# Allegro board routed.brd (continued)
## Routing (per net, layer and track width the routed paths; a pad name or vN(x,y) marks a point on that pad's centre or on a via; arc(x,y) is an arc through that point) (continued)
MEMORY.RA12: length 274.6
  TOP w0.15: v1(78.32,73.41) 80.45,73.41 80.84,73.01 80.84,67.52 83.13,65.23 v1(118.01,65.23) ; 114.48,86.2 113.97,85.68 113.97,80.27 114.48,79.75 U20.19 ; 114.48,86.2 U21.19 ; 114.48,86.2 116.56,86.2 118.14,84.61 118.14,72.99 118.01,72.86 v1(118.01,72.13) ; U18.19 v1(90.48,102.53) ; v1(97.53,99.06) 96.72,98.25 96.72,86.8 v1(95.78,85.86) ; U5.62 68.05,94.46 v1(68.93,93.59) ; U22.19 114.48,102.79 116.14,101.14 117.71,101.14 v1(118.44,101.87) 118.44,117.39 117.43,118.41 114.48,118.41 U23.19 ; U17.19 90.48,90.03 90.7,90.03 v1(90.7,89.3) 92.36,87.65 92.36,80.7 91.96,80.31 91.85,80.31 91.22,79.67 91.22,76.99 90.96,76.73 90.68,76.73 90.48,76.93 U16.19 ; U19.19 v1(90.48,112.56)
  BOTTOM w0.15: v1(90.48,112.56) v1(90.48,102.53) 90.48,101.79 ; 90.48,101.79 90.48,96 88.07,93.59 v1(68.93,93.59) ; 90.48,101.79 92.29,101.79 92.68,102.19 92.68,104.09 96.49,107.9 97.43,107.9 97.83,107.51 97.83,100.1 97.53,99.8 v1(97.53,99.06) ; v1(118.44,101.87) 118.44,87.18 118.01,86.74 v1(118.01,72.13) v1(118.01,65.23) ; v1(95.78,85.86) 94.92,86.72 93.28,86.72 v1(90.7,89.3) 89.85,90.16 82.51,90.16 78.32,85.96 78.32,80.13 78.52,79.94 78.52,74.33 78.32,74.14 v1(78.32,73.41)
MEMORY.RA13: length 256.6
  TOP w0.15: U20.18 v1(115.75,79.84) ; U22.18 115.75,102.62 v1(116.51,101.87) ; 94.14,115.73 94.14,90.33 93.55,89.73 ; 94.14,115.73 92.01,115.73 91.75,115.99 U19.18 ; 94.14,115.73 94.44,116.03 v1(94.44,117.27) ; U5.61 64.28,93.19 v1(63.54,93.93) v1(49.14,93.93) ; v1(116.04,115.29) 116.04,116.03 115.75,116.03 U23.18 ; 93.55,89.73 93.55,80.72 92.53,79.7 92.01,79.7 91.75,79.45 U16.18 ; 93.55,89.73 92.01,89.73 91.75,89.99 U17.18 ; U18.18 91.95,104.22 v1(91.95,102.6) ; U21.18 v1(115.75,92.69)
  BOTTOM w0.15: v1(49.14,93.93) 49.14,94.67 48.73,95.08 48.73,114.7 52.03,118 92.13,118 92.87,117.27 v1(94.44,117.27) 114.06,117.27 v1(116.04,115.29) 116.04,108.31 116.51,107.84 v1(116.51,101.87) 116.51,93.44 v1(115.76,92.69) 115.76,91.96 v1(115.75,79.84) ; v1(63.54,93.93) 64.53,94.92 86.76,94.92 87.78,95.94 87.78,98.65 87.66,98.76 87.66,103.69 89.36,105.38 89.36,112.5 90.15,113.29 90.82,113.29 91.22,112.89 91.22,111.71 91.17,111.67 91.17,106.35 91.95,105.57 v1(91.95,102.6)
MEMORY.RA14: length 227.3
  TOP w0.15: 116.47,96.27 116.01,96.27 115.75,96.01 U22.15 ; 116.47,96.27 116.47,97.83 115.84,98.47 112.31,98.47 111.42,99.35 111.42,105.28 111.55,105.41 115.36,105.41 115.75,105.8 U23.15 ; 116.47,96.27 116.5,96.23 v1(116.5,89.6) ; 115.45,72.82 116.09,73.46 116.96,73.46 117.84,74.35 117.84,83.82 v1(116.5,85.16) 115.75,84.41 U21.15 ; 115.45,72.82 115.75,72.52 U20.15 ; 115.45,72.82 v1(112.46,72.82) ; v1(89.73,101.36) 89.73,105.16 90.88,106.31 91.5,106.31 91.75,106.56 U19.15 ; U16.15 91.75,67.59 ; 91.75,67.59 90.01,67.59 89.75,67.85 v1(89.75,72.76) ; 91.75,67.59 v1(93.98,67.59) ; v1(89.73,96.4) 89.73,93.85 89.99,93.59 91.75,93.59 U18.15 91.75,95.97 93.42,95.97 93.55,95.84 93.55,92.8 93.15,92.41 90.09,92.41 89.97,92.28 89.97,88.67 92.06,86.58 92.06,85.33 v1(91.25,84.52) 91.25,83.52 91.75,83.02 U17.15 ; U5.60 v1(64.31,91.92)
  BOTTOM w0.15: v1(116.5,89.6) v1(116.5,85.16) ; v1(64.31,91.92) 67.01,94.62 86.93,94.62 88.08,95.76 88.08,100.15 87.96,100.26 87.96,102.64 88.36,103.03 89.1,103.03 89.73,102.4 v1(89.73,101.36) v1(89.73,96.4) ; v1(112.46,72.82) 112.46,71.97 109.28,68.8 107.56,68.8 105.53,66.76 105.53,66.75 104.38,65.6 72.41,65.6 71.9,66.11 71.9,67.18 72.92,68.19 92.64,68.19 93.25,67.59 v1(93.98,67.59) ; v1(91.25,84.52) 90.2,84.52 89.69,84.02 89.69,80.06 89.75,80.01 v1(89.75,72.76)
MEMORY.RA15: length 192.9
  TOP w0.15: 93.55,102.09 93.25,101.8 92.71,101.8 88.64,97.73 87.12,97.73 86.86,97.47 v1(86.13,97.47) ; 93.55,102.09 93.84,101.8 93.84,99.11 91.31,96.56 90.99,96.56 90.48,96.06 U18.14 ; 93.55,102.09 93.55,110 92.75,110.79 92.14,110.79 90.48,109.14 U19.14 ; v1(115,96.27) 114.78,96.27 114.27,95.76 114.27,94.78 U22.14 ; 90.48,80.59 U17.14 ; 90.48,80.59 81.1,80.59 80.84,80.85 80.84,82.84 80.72,82.97 79.91,82.97 79.79,82.84 79.79,80.85 79.53,80.59 73.49,80.59 70.32,83.77 70.32,87.86 68.79,89.38 U5.58 63.01,89.38 62.81,89.18 v1(62.07,89.18) ; 90.48,80.59 v1(90.48,79.86) ; 90.48,69.97 94.13,69.97 96.5,67.59 98.37,67.59 98.5,67.72 98.5,69.87 98.89,70.27 99.37,70.27 99.77,69.87 99.77,66.83 100.16,66.43 103.58,66.43 104.84,67.7 104.84,69.68 107.26,72.09 v1(114.48,72.09) U20.14 ; 90.48,69.97 v1(90.48,71.6) ; 90.48,69.97 U16.14 ; v1(115,106.14) 114.99,106.14 114.48,106.65 U23.14 ; v1(115,83.7) 115,82.97 114.48,82.97 U21.14
  BOTTOM w0.15: v1(115,106.14) v1(115,96.27) v1(115,83.7) 115,73.98 114.48,73.46 v1(114.48,72.09) ; v1(62.07,89.18) 62.07,94.12 63.47,95.52 85.49,95.52 86.13,96.15 v1(86.13,97.47) ; v1(90.48,79.86) v1(90.48,71.6)
MEMORY.RCS0: length 65.1
  TOP w0.15: U5.51 62.16,80.92 63.3,79.77 63.65,79.77 ; U17.6 80.33,80.58 79.82,80.07 63.95,80.07 63.65,79.77 ; 63.65,79.77 63.65,73.97 70.25,67.37 73.27,67.37 73.67,66.97 73.67,66.3 73.27,65.91 70.49,65.91 70.06,66.34 67.4,66.34 67.01,65.94 67.01,65.27 67.4,64.87 77.66,64.87 80.33,67.54 U16.6
MEMORY.RCS1: length 47.7
  TOP w0.15: U5.50 60.89,84.19 60.38,84.69 v1(60.16,84.69) ; U18.6 v1(80.33,96.9) ; U19.6 v1(80.33,106.14) ; v1(60.16,89.92) 69.41,89.92 70.05,90.55 v1(70.05,96.9)
  BOTTOM w0.15: v1(70.05,96.9) 79.59,96.9 ; 79.59,96.9 v1(80.33,96.9) ; 79.59,96.9 79.59,105.41 v1(80.33,106.14) ; v1(60.16,89.92) v1(60.16,84.69)
MEMORY.RCS2: length 71.3
  TOP w0.15: v1(72.94,66.64) 70.44,66.64 62.95,74.13 62.95,77.5 59.62,80.83 U5.49 ; U21.6 104.33,80.07 103.59,79.34 v1(103.59,70.4) 103.82,70.4 104.33,69.89 U20.6
  BOTTOM w0.15: v1(72.94,66.64) 73.67,66.64 73.88,66.43 103.19,66.43 103.59,66.83 v1(103.59,70.4)
MEMORY.RCS3: length 154
  TOP w0.15: U23.6 104.33,106.31 105.06,105.57 105.06,101.53 105.36,101.23 ; 105.36,101.23 105.36,98.81 104.33,97.78 U22.6 ; 105.36,101.23 107.98,101.23 108.87,102.12 108.87,105.37 109.5,106 111.83,106 112.47,106.64 112.47,108.73 113.73,110 v1(116.81,110) ; v1(69.28,86.11) 60.13,86.11 58.35,84.33 U5.48
  BOTTOM w0.15: v1(116.81,110) 116.81,109.27 117.24,108.83 117.24,78.82 115.91,77.48 115.91,70.8 109.81,64.7 72.33,64.7 69.28,67.75 v1(69.28,86.11)
MEMORY.RD0: length 243.3
  TOP w0.15: v1(105.59,97.27) U22.7 105.59,93.56 105.85,93.31 113.99,93.31 115,92.29 115,90.01 116.15,88.87 117.25,88.87 117.55,89.17 ; 111.71,67.59 111.41,67.59 111.41,69.84 109.76,71.49 107.12,71.49 105.59,69.97 U20.7 ; 111.71,67.59 117.47,67.59 118.75,68.87 118.75,87.97 117.55,89.17 ; 111.71,67.59 111.71,66.8 110.44,65.53 83.37,65.53 81.59,67.31 U16.7 ; v1(57.31,117.27) 57.31,113 57.08,112.76 U5.81 ; v1(92.5,109.76) 92.5,106.59 91.62,105.7 91.22,105.31 91.22,101.75 87.66,98.2 83.25,98.2 81.59,96.55 U18.7 ; 117.55,89.17 117.55,97.23 114.37,100.4 v1(112.68,100.4)
  BOTTOM w0.15: v1(112.68,100.4) 112.33,100.75 112.33,113.43 109.15,116.6 97.61,116.6 97.55,116.54 91.07,116.54 90.33,117.27 v1(57.31,117.27) ; v1(105.59,97.27) 105.59,93.16 104.71,92.27 103.89,92.27 102.24,93.92 102.24,112.99 101.73,113.49 96.24,113.49 v1(92.5,109.76)
MEMORY.RD1: length 140.1
  TOP w0.15: v1(85.3,96.4) 85.3,94.78 ; 85.3,94.78 U18.10 ; 85.3,94.78 84.88,94.78 84.88,89.99 85.14,89.73 85.53,89.73 85.92,90.13 85.92,92.15 86.94,93.16 v1(92.79,93.16) ; U22.10 109.41,95.97 109.69,95.97 v1(109.69,96.7) ; v1(61.62,99.3) 55.81,105.12 U5.82 ; v1(109.41,70.7) U20.10 109.41,67.53 108.01,66.13 86.8,66.13 85.41,67.53 U16.10
  BOTTOM w0.15: v1(109.41,70.7) 111.16,72.45 111.16,85.42 110.95,85.62 ; v1(92.79,93.16) 93.82,94.19 98.16,94.19 100.83,91.53 100.83,89.01 104.51,85.33 110.65,85.33 110.95,85.62 ; 110.95,85.62 110.95,87.65 109.69,88.9 v1(109.69,96.7) ; v1(85.3,96.4) 84.93,96.02 64.9,96.02 v1(61.62,99.3)
MEMORY.RD2: length 231.9
  TOP w0.15: U18.23 85.41,103.11 85.88,102.64 v1(85.88,102.6) ; U22.23 109.41,102.97 109.85,102.52 v1(109.85,101.79) ; U20.23 109.41,76.39 110.04,75.75 v1(112.03,75.75) ; v1(54.54,108.24) U5.83 ; v1(72.95,73.75) 72.95,74.48 ; 72.95,74.48 v1(64.68,74.48) ; 72.95,74.48 73.25,74.78 83.74,74.78 84.89,75.92 84.89,76.28 85.41,76.8 U16.23
  BOTTOM w0.15: v1(109.85,101.79) 110.93,101.79 111.73,101 111.73,75.02 ; 111.73,75.02 111.73,71.81 109.31,69.4 107.17,69.4 104.62,66.85 104.62,66.79 103.74,65.91 72.6,65.91 72.2,66.3 72.2,67.01 73.09,67.9 88.55,67.9 89.58,66.86 94.61,66.86 95.01,67.26 95.01,67.7 94.22,68.5 75.87,68.5 72.95,71.42 v1(72.95,73.75) ; 111.73,75.02 112.03,75.02 v1(112.03,75.75) ; 58.01,108.24 80.24,108.24 v1(85.88,102.6) ; 58.01,108.24 58.01,83.76 59.4,82.36 59.46,82.36 63.65,78.17 63.65,75.51 v1(64.68,74.48) ; 58.01,108.24 v1(54.54,108.24)
MEMORY.RD3: length 278.1
  TOP w0.15: 105.59,74.72 U20.26 ; 105.59,74.72 v1(117.11,74.72) ; 105.59,74.72 v1(104.33,74.72) ; v1(60.58,65.73) 65.59,65.73 66.83,64.5 118.35,64.5 118.75,64.89 118.75,65.97 117.86,66.86 v1(117.11,66.86) ; U22.26 105.59,105.77 106.11,106.29 106.11,110.07 107.51,111.46 v1(116.92,111.46) ; U16.26 81.59,79.41 87.07,79.41 87.19,79.28 87.19,77.39 88.85,75.74 95.29,75.74 95.68,75.34 95.68,74.69 95.18,74.18 v1(94.13,74.18) ; U18.26 81.59,105.5 82.1,106 85.29,106 85.92,106.64 85.92,110.78 86.81,111.67 86.91,111.67 87.31,112.07 87.31,118.2 86.8,118.7 57.08,118.7 53.27,114.89 U5.84 v1(53.27,109.03)
  BOTTOM w0.15: v1(53.27,109.03) 53.27,85.2 57.21,81.26 57.28,81.26 60.58,77.96 v1(60.58,65.73) ; v1(94.13,74.18) 103.05,74.18 103.59,74.72 v1(104.33,74.72) ; v1(116.92,111.46) 116.92,110.73 117.14,110.73 117.54,110.33 117.54,76.86 117.11,76.44 v1(117.11,74.72) v1(117.11,66.86)
MEMORY.RD4: length 154
  TOP w0.15: U17.7 81.59,83.65 83.25,85.3 88.83,85.3 v1(90.43,83.7) ; U23.7 105.59,109.03 104.33,110.3 v1(100.78,110.3) ; v1(104.31,83.4) 105.2,83.4 105.59,83 U21.7 ; U19.7 v1(81.59,110.12) ; v1(56.55,115.02) v1(56.55,109.31) ; U5.1 v1(52,115.02)
  BOTTOM w0.15: v1(104.31,83.4) 100.53,83.4 ; 100.53,83.4 100.23,83.1 100.23,76.53 98.83,75.14 97.38,75.14 96.58,75.93 96.58,77.54 v1(90.43,83.7) ; 100.53,83.4 100.53,91.31 98.24,93.59 95.9,93.59 94.74,92.43 92.45,92.43 92.06,92.83 92.06,93.49 95.99,97.43 96.99,97.43 98.26,98.7 98.26,108.36 ; 98.26,108.36 98.84,108.36 v1(100.78,110.3) ; 98.26,108.36 92.36,108.36 91.47,109.25 91.47,111.37 91.52,111.41 91.52,113.08 91.01,113.59 89.9,113.59 88.76,112.45 88.76,110.61 87.17,109.02 81.85,109.02 81.59,109.28 v1(81.59,110.12) 80.77,110.12 80.45,110.43 57.67,110.43 v1(56.55,109.31) ; v1(52,115.02) v1(56.55,115.02)
MEMORY.RD5: length 188
  TOP w0.15: v1(104.31,93) 110.56,93 111.19,92.37 111.19,88.39 109.92,87.12 109.91,87.12 109.41,86.62 U21.10 v1(109.41,80.16) ; U19.10 85.41,109.64 83.37,111.67 v1(79.85,111.67) ; v1(88.48,84.56) 86.99,84.56 85.41,82.98 U17.10 ; v1(60.26,116.3) v1(60.26,113.55) ; U5.2 v1(50.73,113.55) ; U23.10 v1(109.41,110.32)
  BOTTOM w0.15: v1(79.85,111.67) 62.14,111.67 v1(60.26,113.55) v1(50.73,113.55) ; v1(109.41,80.16) 108.67,80.16 107.96,80.87 105.55,80.87 101.99,77.31 101.99,77.25 99.58,74.84 96.28,74.84 95.08,76.04 94.46,76.04 92.55,74.13 92.55,72.52 90.9,70.87 90.06,70.87 88.29,72.64 88.29,79.88 88.59,80.19 88.59,83.72 88.48,83.83 v1(88.48,84.56) ; v1(60.26,116.3) 89.64,116.3 89.71,116.24 99.95,116.24 100.01,116.3 108.97,116.3 111.25,114.02 111.25,111.34 110.23,110.32 v1(109.41,110.32) 109.41,106.58 105.06,102.23 105.06,101.12 104.17,100.23 104.11,100.23 103.72,99.84 103.72,94.33 104.31,93.74 v1(104.31,93)
MEMORY.RD6: length 146.1
  TOP w0.15: v1(97.02,107.17) v1(97.02,112.46) ; U17.23 85.41,92.45 86.42,93.46 88.21,93.46 88.47,93.72 88.47,96.29 89.61,97.43 90.88,97.43 v1(93.11,99.66) ; v1(108.96,88.27) 108.96,89 109.41,89.44 U21.23 ; U23.23 v1(109.41,114.23) ; U19.23 85.41,116.03 85.17,115.8 v1(85.17,114.41) ; U5.3 v1(49.46,114.28)
  BOTTOM w0.15: 91.52,114.11 86.2,114.11 85.9,114.41 v1(85.17,114.41) 61.66,114.41 61.53,114.28 v1(49.46,114.28) ; 91.52,114.11 91.64,114.23 v1(109.41,114.23) ; 91.52,114.11 91.82,113.81 91.82,110.81 91.77,110.77 91.77,109.42 92.17,109.02 93.58,109.02 v1(97.02,112.46) 98.06,112.46 98.79,113.19 101.54,113.19 101.94,112.8 101.94,93.79 104.23,91.5 106.8,91.5 108.96,89.34 v1(108.96,88.27) ; v1(97.02,107.17) 93.11,103.26 v1(93.11,99.66)
MEMORY.RD7: length 154.9
  TOP w0.15: v1(62.45,100.43) 57.62,105.26 57.62,115.66 v1(58.49,116.54) 58.49,117.37 57.86,118 56.92,118 55.27,116.35 55.27,107.84 54.64,107.21 50.6,107.21 48.19,109.62 U5.4 ; U21.26 v1(105.59,89.6) ; v1(77.7,97.63) 78.47,97.63 79.35,96.74 79.35,96.11 79.66,95.81 79.66,93.8 80.45,93 81.09,93 81.59,92.5 U17.26 ; v1(101.21,112.46) 105.09,112.46 105.59,112.97 v1(105.59,115.27) U23.26 ; U19.26 v1(81.59,115.22)
  BOTTOM w0.15: 81.59,116 61.81,116 61.38,115.57 59.47,115.57 v1(58.49,116.54) ; 81.59,116 v1(81.59,115.22) ; 81.59,116 85.77,116 87.23,114.53 104.86,114.53 v1(105.59,115.27) ; v1(101.21,112.46) 101.21,111.73 101.51,111.43 101.51,93.65 104.56,90.6 104.6,90.6 v1(105.59,89.6) ; v1(62.45,100.43) 62.45,99.02 64.23,97.24 66.94,97.24 67.34,97.63 v1(77.7,97.63)
MEMORY.RWE: length 230.9
  TOP w0.15: v1(114.17,110.73) 112.33,110.73 110.67,109.08 U23.11 110.67,106.56 110.42,106.31 108.47,106.31 108.33,106.16 v1(107.6,106.16) ; v1(88.04,115.27) 88.04,112.26 87.15,111.37 87.07,111.37 86.67,110.98 U19.11 v1(86.67,105.91) ; v1(87.86,83.4) 87.07,83.4 86.67,83 U17.11 ; v1(87.04,96.47) 87.04,94.78 U18.11 ; 86.67,69.97 85.01,69.97 84.88,69.84 84.88,67.61 86.66,65.83 109.64,65.83 v1(110.67,66.86) U20.11 ; 86.67,69.97 v1(86.67,71.6) ; 86.67,69.97 U16.11 ; U5.56 v1(62.81,86.84) ; U22.11 110.67,96.03 112.07,97.43 v1(115.74,97.43) ; U21.11 110.67,80.02 111.3,79.39 111.3,77.29 111.56,77.03 112.34,77.03 112.47,77.16 112.47,79.15 112.72,79.41 113.69,79.41 113.95,79.15 113.95,76.92 114.17,76.7 v1(114.17,75.78)
  BOTTOM w0.15: v1(86.67,71.6) 87.86,72.78 v1(87.86,83.4) ; v1(115.74,97.43) 115.74,106.47 115.34,106.87 114.17,106.87 ; 114.17,106.87 v1(114.17,75.78) 114.17,74.35 113.52,73.7 113.52,69.7 v1(110.67,66.86) ; 114.17,106.87 v1(114.17,110.73) ; v1(107.6,106.16) 105.83,107.93 105.83,109.78 107.1,111.05 109.81,111.05 110.95,112.2 110.95,113.84 108.79,116 102.44,116 101.71,115.27 v1(88.04,115.27) ; v1(86.67,105.91) 86.67,105.18 87.31,104.55 87.31,97.94 87.04,97.67 v1(87.04,96.47) 85.79,95.22 63.7,95.22 62.81,94.33 v1(62.81,86.84)
MRD: length 38.8
  BOTTOM w0.15: U2.9 40.95,61.27 40.95,57.48 36.76,53.28 13.33,53.28 13.09,53.52 J1.46
MWR: length 47.9
  BOTTOM w0.15: J1.45 13.09,50.98 13.1,50.99 32.86,50.99 33.1,50.74 41.43,50.74 43.48,52.8 43.91,52.8 45.17,54.06 45.17,65.69 U2.10
N00036_DATA_DAAMP: length 32.6
  TOP w0.15: U8.8 v1(85.13,42.17) ; U8.5 v1(85.13,38.36) ; U10.5 v1(84.97,44.41)
  BOTTOM w0.15: L4.2 92.58,31.3 92.58,33.24 90.99,34.83 90.67,34.83 ; R7.1 90.67,35.5 90.67,34.83 ; 86.49,38 86.19,37.7 86.19,35.16 86.83,34.52 90.67,34.52 90.67,34.83 ; 86.49,38 86.13,38.36 v1(85.13,38.36) v1(85.13,42.17) 85.13,43.51 84.97,43.67 v1(84.97,44.41) ; 86.49,38 R6.1
N00036_DATA_DAAMP1: length 34
  TOP w0.15: U13.5 v1(85.27,24.48) ; U11.5 v1(85.22,18.44) ; U11.8 v1(84.54,22.25)
  BOTTOM w0.15: 86.63,18.44 86.63,19.08 87.77,20.22 90.09,20.22 90.97,19.33 90.97,15.58 ; 86.63,18.44 v1(85.22,18.44) 85.22,19.18 85.27,19.23 85.27,22.25 ; 86.63,18.44 86.99,18.08 R8.1 ; 85.27,22.25 v1(85.27,24.48) ; 85.27,22.25 v1(84.54,22.25) ; L6.2 93.05,10.91 93.05,13.5 90.97,15.58 ; 90.97,15.58 R9.1
N00038_DATA_DAAMP: length 25.1
  TOP w0.15: U8.4 v1(84.35,37.09)
  BOTTOM w0.15: 91.08,31.61 91.08,31.19 93.74,28.52 94.85,28.52 95.36,29.03 95.36,31.02 L3.2 ; 91.08,31.61 91.38,31.61 91.38,33 C8.1 ; 91.08,31.61 85.75,31.61 84.35,33.01 v1(84.35,37.09)
N00038_DATA_DAAMP1: length 15.2
  TOP w0.15: U11.4 83.97,17.17 84.77,16.38 84.77,16.25 87.94,13.08 v1(91.72,13.08) 92.72,12.08 L5.2
  BOTTOM w0.15: C11.1 v1(91.72,13.08)
N00044_DATA_DAAMP: length 8.5
  TOP w0.15: U10.1 90.77,40.59 90.77,39.97 91.4,39.34 v1(92.31,39.34)
  BOTTOM w0.15: v1(92.31,39.34) 93.04,39.34 93.64,39.93 U9.2
N00044_DATA_DAAMP1: length 5.2
  TOP w0.15: U13.1 94.06,20.67 94.72,20.01 96.93,20.01
N00060_DATA_DAAMP: length 20
  TOP w0.15: U8.6 v1(87.06,39.64)
  BOTTOM w0.15: U9.3 97.55,37.63 92.93,37.63 91.28,39.28 91.28,39.47 89.12,41.63 88.21,41.63 87.06,40.48 v1(87.06,39.64)
N00060_DATA_DAAMP1: length 20
  TOP w0.15: U11.6 85.06,19.71 85.95,18.82 85.95,17.14 86.84,16.25 96.1,16.25 U12.3
N282866_DATA_DAAMP: length 6.4
  TOP w0.15: U10.8 v1(88.92,40.59)
  BOTTOM w0.15: v1(88.92,40.59) 89.66,40.59 90.67,39.58 90.67,38 R6.2
N282866_DATA_DAAMP1: length 6.7
  TOP w0.15: U13.8 88.09,20.67 v1(88.09,19.49)
  BOTTOM w0.15: R8.2 90.67,18.08 90.67,19.09 90.28,19.49 v1(88.09,19.49)
N282912_DATA_DAAMP: length 10.3
  TOP w0.15: U10.2 90.74,41.86 89.95,41.07 89.95,38.52 v1(86.93,35.5)
  BOTTOM w0.15: R7.2 v1(86.93,35.5)
N282912_DATA_DAAMP1: length 10.6
  TOP w0.15: v1(86.89,17.29) 87.72,17.29 90.52,20.08 90.52,21.74 90.72,21.94 U13.2
  BOTTOM w0.15: R9.2 87.29,15.58 86.89,15.98 v1(86.89,17.29)
NCS: length 14.5
  TOP w0.15: U7.4 30.84,108.97 38.79,108.97 39.3,109.47 U5.11
OE: length 33.3
  TOP w0.15: U7.3 30.21,103.58 32.44,101.34 39.28,101.34 41.82,98.81 41.82,86.27 41.06,85.51 40.45,85.51 39.56,84.62 39.56,84.55 39.31,84.3 U5.32
OUTA: length 18.3
  TOP w0.15: U9.6 101.07,45.3 100.05,46.32 97.55,46.32 94.5,43.27 L1.1
OUTB: length 18.3
  BOTTOM w0.15: L2.1 94.5,23.35 97.55,26.4 100.05,26.4 101.07,25.38 U12.6
Q0: length 6
  TOP w0.15: U6.18 72.91,60.67 73.09,60.5 R1.1
Q1: length 5.9
  TOP w0.15: R2.1 73.05,58 72.91,58.13 U6.16
Q2: length 5.9
  TOP w0.15: R3.1 73.01,55.5 72.91,55.59 U6.14
Q3: length 5.9
  TOP w0.15: U6.12 72.91,53.05 72.97,53 R4.1
RDY: length 41
  TOP w0.15: U2.23 37.68,47.85 v1(37.68,58.61)
  BOTTOM w0.15: J1.50 13.69,62.07 13.69,61.16 16.49,58.37 37.44,58.37 v1(37.68,58.61)
RESET: length 59
  TOP w0.15: U5.15 v1(31.16,105.89)
  BOTTOM w0.15: v1(31.16,105.89) 31.16,105.06 28.36,102.27 13.31,102.27 10.77,99.72 10.77,72.61 J1.53
SEL: length 50.9
  TOP w0.15: U5.13 v1(44.75,108.43)
  BOTTOM w0.15: U2.14 37.55,70.58 37.55,87.82 40.59,90.87 40.7,90.87 46.41,96.58 46.41,100.15 44.75,101.8 v1(44.75,108.43)
V+12: length 195.1
  TOP w0.4: J1.64 J1.63 ; 99,26.52 101.06,26.52 103.47,28.94 v1(103.47,33.17) ; 99,26.52 93.09,26.52 92.46,25.9 v1(90.74,25.9) 90.74,24.48 U13.4 ; 99,26.52 U12.7 ; v1(44.74,96.31) 46.01,95.04 v1(58.99,95.04) ; U10.4 v1(89.92,44.41)
  BOTTOM w0.4: 89.62,45.51 90.55,46.45 99,46.45 ; 89.62,45.51 80.61,45.51 78.7,43.61 ; 89.62,45.51 89.92,45.51 v1(89.92,44.41) ; v1(44.74,96.31) 13.86,96.31 13.47,96.7 J1.63 ; 99,46.45 100.93,46.45 103.47,43.91 v1(103.47,33.17) ; 99,46.45 U9.7 ; 78.7,43.61 75.08,43.61 65.81,52.88 65.81,77.45 60.22,83.04 60.13,83.04 58.99,84.18 v1(58.99,95.04) ; 78.7,43.61 79,43.31 C9.1 ; C12.1 79,23.36 81.54,25.9 v1(90.74,25.9)
VCLKA: length 84.2
  TOP w0.2: U8.11 74.67,44.72 75.07,44.32 75.07,42.08 74.56,41.57 v1(67.14,41.57) 67.14,33.92 67.77,33.28 U14.11 ; v1(60.58,63.01) 43.87,63.01 40.57,66.31 U5.34
  BOTTOM w0.2: v1(67.14,41.57) 62.04,46.67 62.04,55.66 60.58,57.11 v1(60.58,63.01)
VCLKC: length 100
  TOP w0.2: v1(49.7,29.44) v1(49.7,31.77) ; U11.11 71.69,24.79 70.89,25.6 67.06,25.6 66.66,25.2 v1(66.66,23.58) 66.66,14.51 67.81,13.36 U15.11
  BOTTOM w0.2: v1(66.66,23.58) 60.8,29.44 v1(49.7,29.44) ; R5.2 49.7,88.5 v1(49.7,31.77)
VD0: length 88.8
  TOP w0.15: 56.08,43.74 56.08,61.95 ; 56.08,43.74 55.65,43.31 v1(55.65,27.5) ; 56.08,43.74 56.38,43.45 U14.2 ; 56.08,61.95 v1(46.92,61.95) ; 56.08,61.95 U6.2 ; v1(46.92,80.71) U5.39 ; U15.2 v1(57.79,23.52)
  BOTTOM w0.15: R13.2 v1(55.65,27.5) 57.79,25.36 v1(57.79,23.52) ; v1(46.92,61.95) v1(46.92,80.71)
VD1: length 100.7
  TOP w0.15: v1(64.13,61.31) 61.18,61.31 60.98,61.12 60.98,60.67 ; v1(54.9,84.79) 48.59,84.79 48.19,84.4 U5.40 ; v1(54.32,25) 55.22,25 56.48,26.27 56.48,40.27 58.39,42.17 U14.3 61.2,42.17 61.2,46.26 60.31,47.15 60.3,47.15 56.48,50.96 56.48,59.41 57.76,60.67 60.98,60.67 ; U6.3 60.98,60.67 ; U15.3 v1(57.79,22.25)
  BOTTOM w0.15: v1(57.79,22.25) 56.23,22.25 54.32,24.16 v1(54.32,25) R17.2 ; v1(64.13,61.31) 62.95,62.49 62.95,77.6 58.89,81.66 58.03,81.66 v1(54.9,84.79)
VD2: length 87.4
  TOP w0.15: U6.4 v1(57.72,59.41) 56.89,58.57 56.89,52.58 60.31,49.15 60.34,49.15 61.99,47.5 61.99,41.7 61.2,40.91 U14.4 58.47,40.91 56.89,39.32 56.89,22.8 56.59,22.5 ; 56.59,22.5 v1(49.72,22.5) ; 56.59,22.5 56.59,22 57.6,20.98 U15.4 ; v1(57.72,71.44) 56.83,71.44 49.46,78.8 U5.41
  BOTTOM w0.15: v1(57.72,71.44) v1(57.72,59.41) ; R12.2 v1(49.72,22.5)
VD3: length 96.8
  TOP w0.15: U6.5 v1(64.13,58.13) 64.13,40.2 63.26,39.34 ; U15.5 59.84,19.93 58.05,19.93 v1(57.98,20) ; 63.26,39.34 62.96,39.64 U14.5 ; 63.26,39.34 v1(63.26,20) ; v1(61.82,77.44) 51.62,77.44 50.73,78.33 U5.42
  BOTTOM w0.15: v1(63.26,20) v1(57.98,20) R16.2 ; v1(64.13,58.13) 61.82,60.45 v1(61.82,77.44)
VD4: length 94.5
  TOP w0.15: U14.6 58.48,38.36 58.09,37.97 v1(58.09,31.82) 58.09,29.64 60.37,27.35 60.4,27.35 61.2,26.55 61.2,18.44 U15.6 v1(53.72,18.44) ; U5.43 v1(52,78.33) ; U6.6 v1(58.52,56.87)
  BOTTOM w0.15: v1(53.72,18.44) 52.77,17.5 R11.2 ; 57.25,56.56 57.25,32.66 v1(58.09,31.82) ; 57.25,56.56 52,61.82 v1(52,78.33) ; 57.25,56.56 57.55,56.87 v1(58.52,56.87)
VD5: length 96.6
  TOP w0.15: U14.7 61.54,37.09 62.43,36.21 v1(62.43,33.76) v1(62.43,18.01) 61.59,17.17 U15.7 ; U6.7 v1(58.92,55.59) ; v1(53.58,79.6) 53.58,80.83 53.27,81.14 U5.44
  BOTTOM w0.15: v1(62.43,18.01) 59.42,15 R15.2 ; v1(62.43,33.76) 60.67,35.51 60.67,47.47 58.92,49.23 v1(58.92,55.59) 59.35,56.03 59.35,75.15 54.91,79.6 v1(53.58,79.6)
VD6: length 89.7
  TOP w0.15: v1(57.72,58.13) 57.72,57.3 57.69,57.27 57.69,55.59 58.95,54.33 v1(60.78,54.33) U6.8 ; U15.8 58.48,15.9 ; 58.48,15.9 56.72,15.9 v1(53.32,12.5) ; 58.48,15.9 58.48,17.68 58.61,17.8 61.2,17.8 61.59,18.2 v1(61.59,35.83) U14.8 ; U5.45 v1(54.54,78.7)
  BOTTOM w0.15: v1(57.72,58.13) 54.54,61.31 v1(54.54,78.7) ; v1(60.78,54.33) 60.78,53.42 61.59,52.61 v1(61.59,35.83) ; R10.2 v1(53.32,12.5)
VD7: length 110.2
  TOP w0.15: U15.9 v1(64.83,14.63) ; U5.46 v1(55.81,80.43) ; v1(60.76,28.18) 60.76,29.02 61.2,29.45 61.2,34.55 U14.9 58.48,34.55 58.48,37.6 58.61,37.73 61,37.73 61.2,37.92 61.2,38.87 61.07,39 58.68,39 58.48,39.19 58.48,40.14 58.61,40.27 61.16,40.27 63.7,42.8 63.7,53.05 U6.9 v1(59.75,53.05)
  BOTTOM w0.15: v1(59.75,53.05) 59.75,76.49 v1(55.81,80.43) ; v1(60.76,28.18) 64.83,24.12 v1(64.83,14.63) 60.2,10 R14.2
VREF: length 25.4
  TOP w0.15: R18.1 103.48,10.5 102.97,11.01 102.97,11.1 L5.1
  BOTTOM w0.15: L5.1 104.12,14.2 104.12,29.88 L3.1
WAIT: length 49.7
  TOP w0.15: v1(34.47,77.02) 35.24,77.02 39.3,81.08 U5.33
  BOTTOM w0.15: v1(34.47,77.02) 34.47,64.2 30.41,60.14 27.74,60.14 26.56,58.96 23.45,58.96 21.67,60.74 21.67,62.72 19.64,64.75 19.52,64.75 18.05,66.22 J1.51
WSTAT: length 41.7
  TOP w0.15: U6.11 v1(68.55,51.78) ; U5.57 v1(68.55,88.11)
  BOTTOM w0.15: v1(68.55,51.78) v1(68.55,88.11)
N14843: length 3.2
  BOTTOM w0.15: C19.1 R16.1
N14849: length 3.2
  BOTTOM w0.15: C15.1 R12.1
N14853: length 3.2
  BOTTOM w0.15: C20.1 R17.1
N14855: length 3.2
  BOTTOM w0.15: C16.1 R13.1
N15143: length 3.2
  BOTTOM w0.15: C17.1 R14.1
N15151: length 3.2
  BOTTOM w0.15: C13.1 R10.1
N15155: length 3.2
  BOTTOM w0.15: C18.1 R15.1
N15161: length 3.2
  BOTTOM w0.15: C14.1 R11.1
N58063: length 4.2
  TOP w0.15: U8.12 U14.19
N58118: length 4.2
  TOP w0.15: U8.13 U14.18
N58173: length 4.2
  TOP w0.15: U8.14 U14.17
N58228: length 4.2
  TOP w0.15: U8.15 U14.16
N58283: length 4.2
  TOP w0.15: U8.16 U14.15
N58338: length 4.2
  TOP w0.15: U8.17 U14.14
N58393: length 4.2
  TOP w0.15: U8.18 U14.13
N58448: length 4.2
  TOP w0.15: U8.19 U14.12
N58834: length 4.2
  TOP w0.15: U11.12 U15.19
N58889: length 4.2
  TOP w0.15: U11.13 U15.18
N58944: length 4.2
  TOP w0.15: U11.14 U15.17
N58999: length 4.2
  TOP w0.15: U11.15 U15.16
N59054: length 4.2
  TOP w0.15: U11.16 U15.15
N59109: length 4.2
  TOP w0.15: U11.17 U15.14
N59164: length 4.2
  TOP w0.15: U11.18 U15.13
N59219: length 4.2
  TOP w0.15: U11.19 U15.12
N409523: length 8.4
  TOP w0.15: U5.37 v1(44.38,88.5)
  BOTTOM w0.15: R5.1 v1(44.38,88.5)

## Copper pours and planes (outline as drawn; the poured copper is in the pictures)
GND on GND1, GND2: 21,1.41 21,9 20.41,10.41 19,11 1.41,11 1,11.41 1,108.59 1.41,109 19,109 20.41,109.59 21,111 21,118.59 21.41,119 118.59,119 119,118.59 119,1.41 118.59,1 21.41,1 ; 2 cut-outs
VCC on VCC1, VCC2: 21,1.41 21,9 20.41,10.41 19,11 1.41,11 1,11.41 1,108.59 1.41,109 19,109 20.41,109.59 21,111 21,118.59 21.41,119 118.59,119 119,118.59 119,1.41 118.59,1 21.41,1 ; 2 cut-outs
